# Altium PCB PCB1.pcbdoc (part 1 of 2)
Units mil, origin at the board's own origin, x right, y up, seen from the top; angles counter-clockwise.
Board outline 2755.9 x 2755.9 mil, 4 copper layers (Top Layer, GND02, PWR03, Bottom Layer), stack 64.1 mil thick; 209 components, 118 nets, 572 pads, 665 vias.
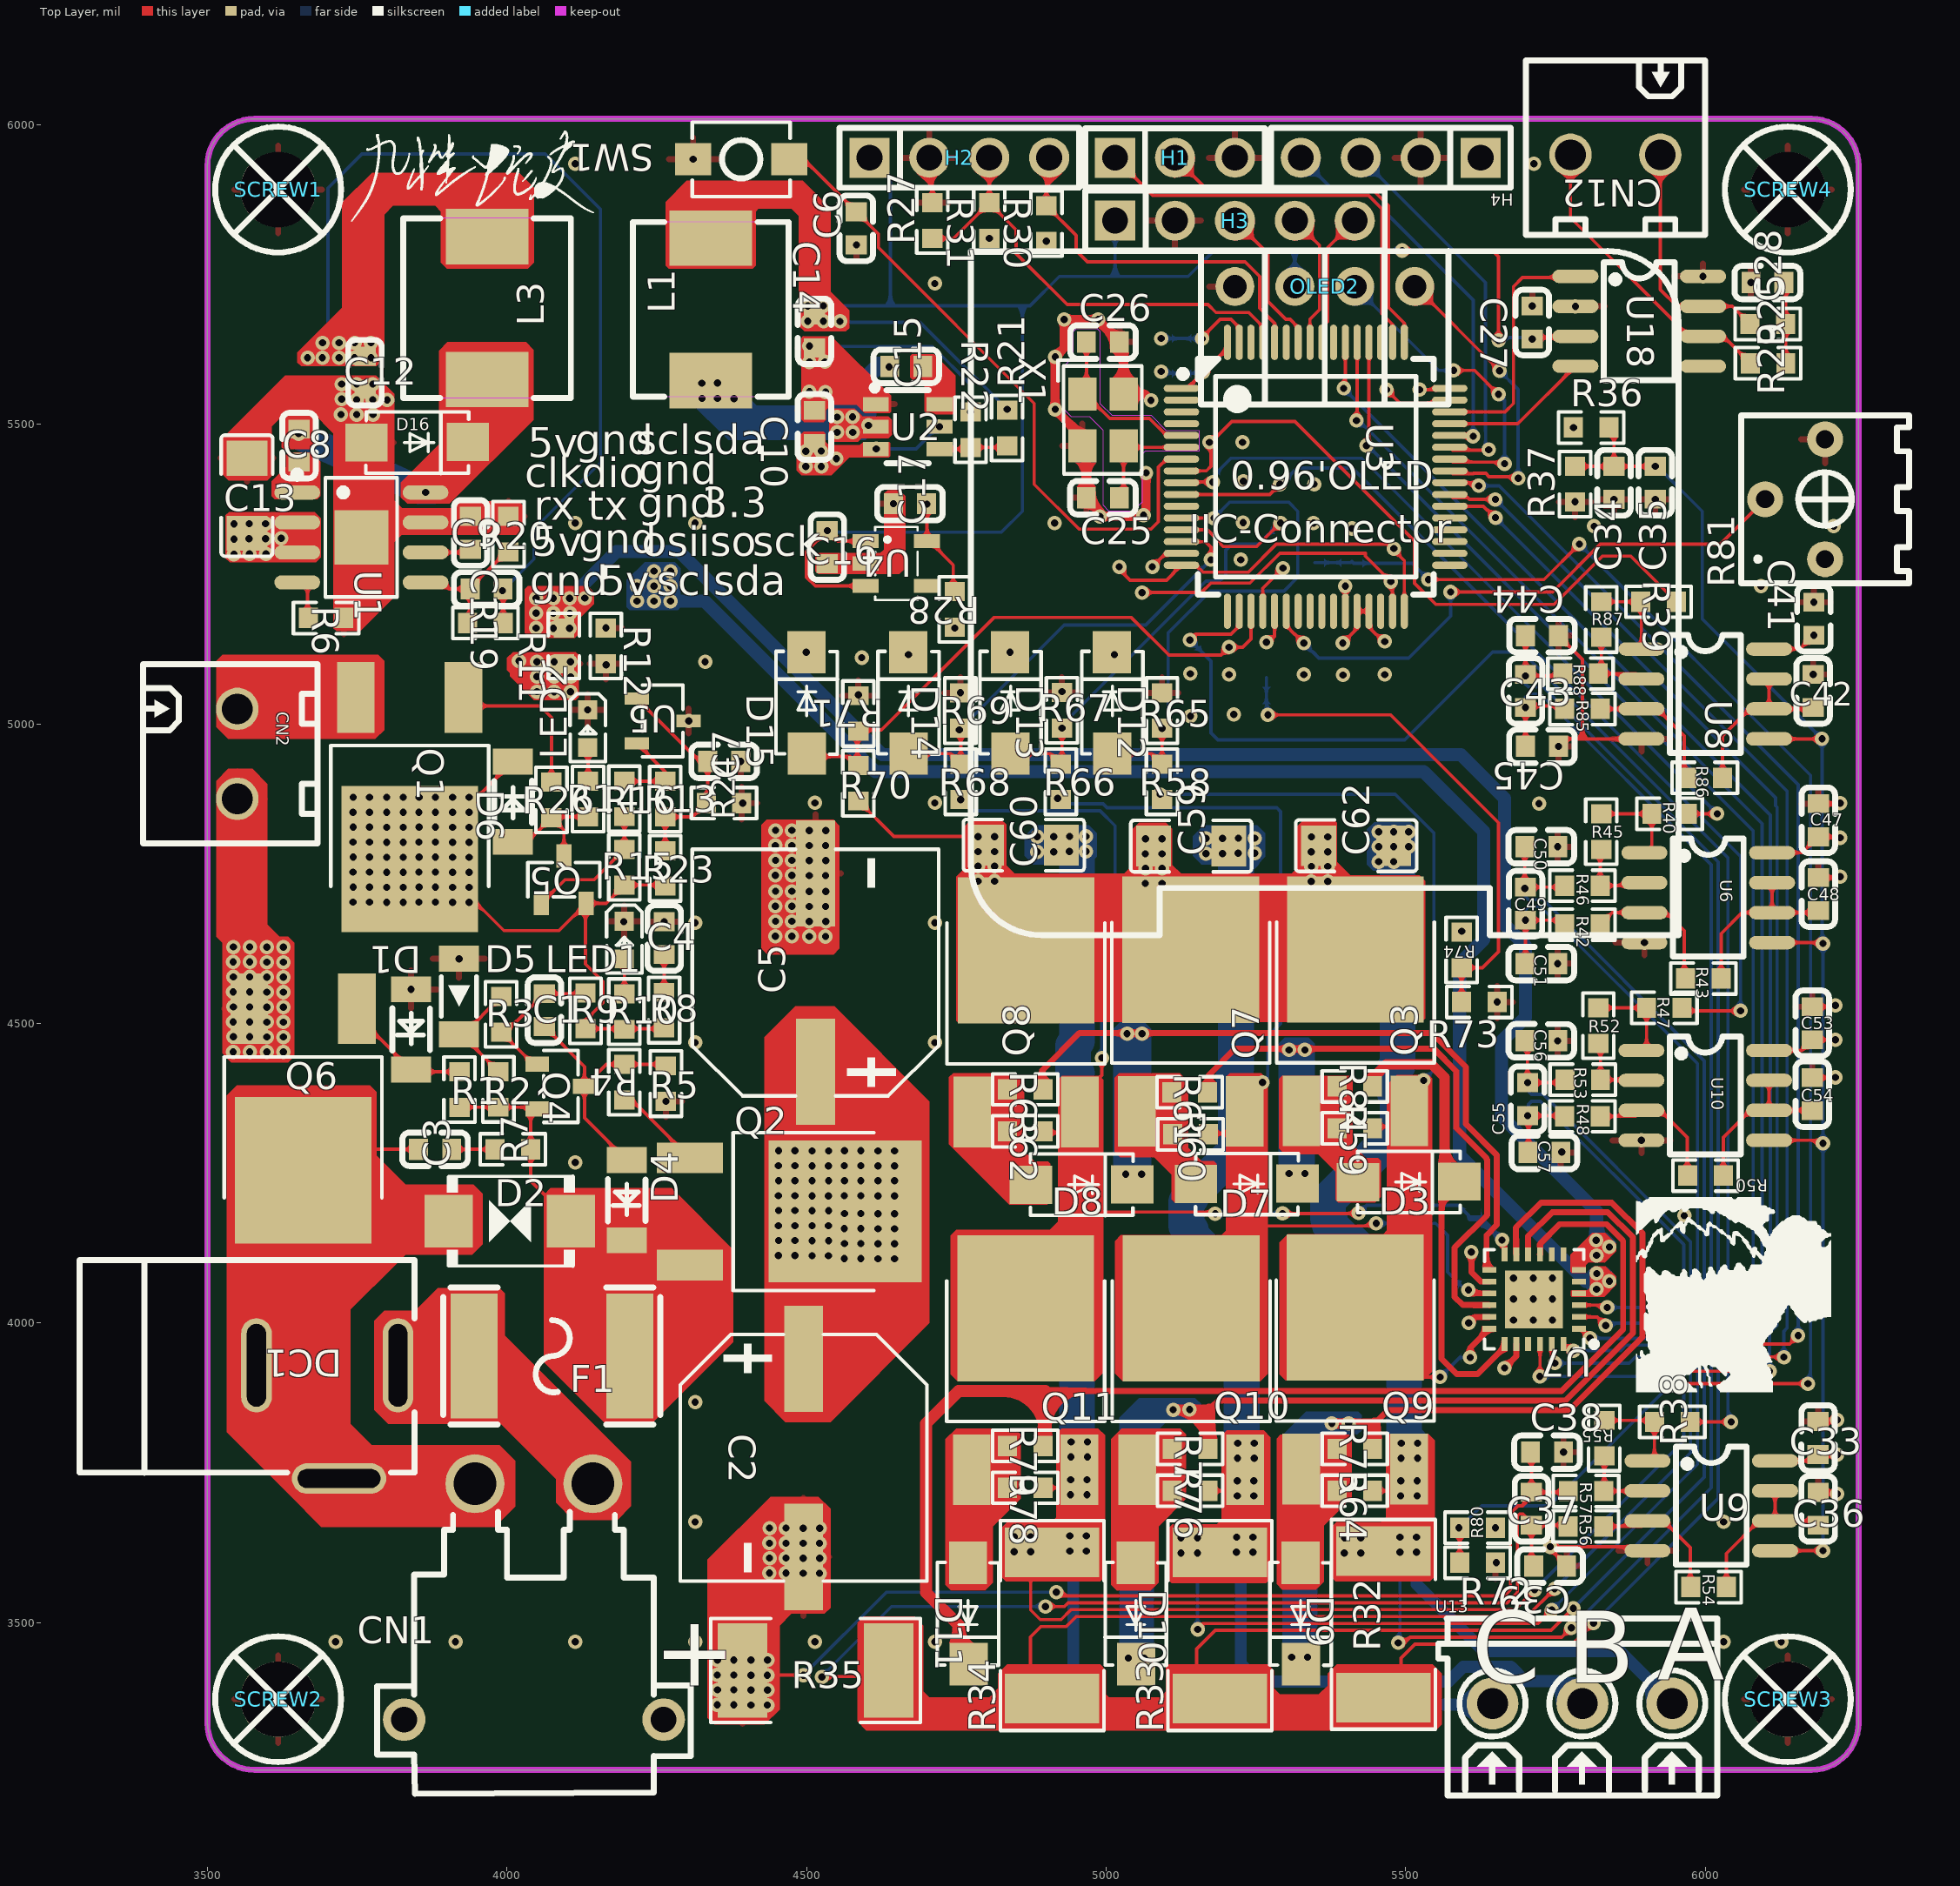
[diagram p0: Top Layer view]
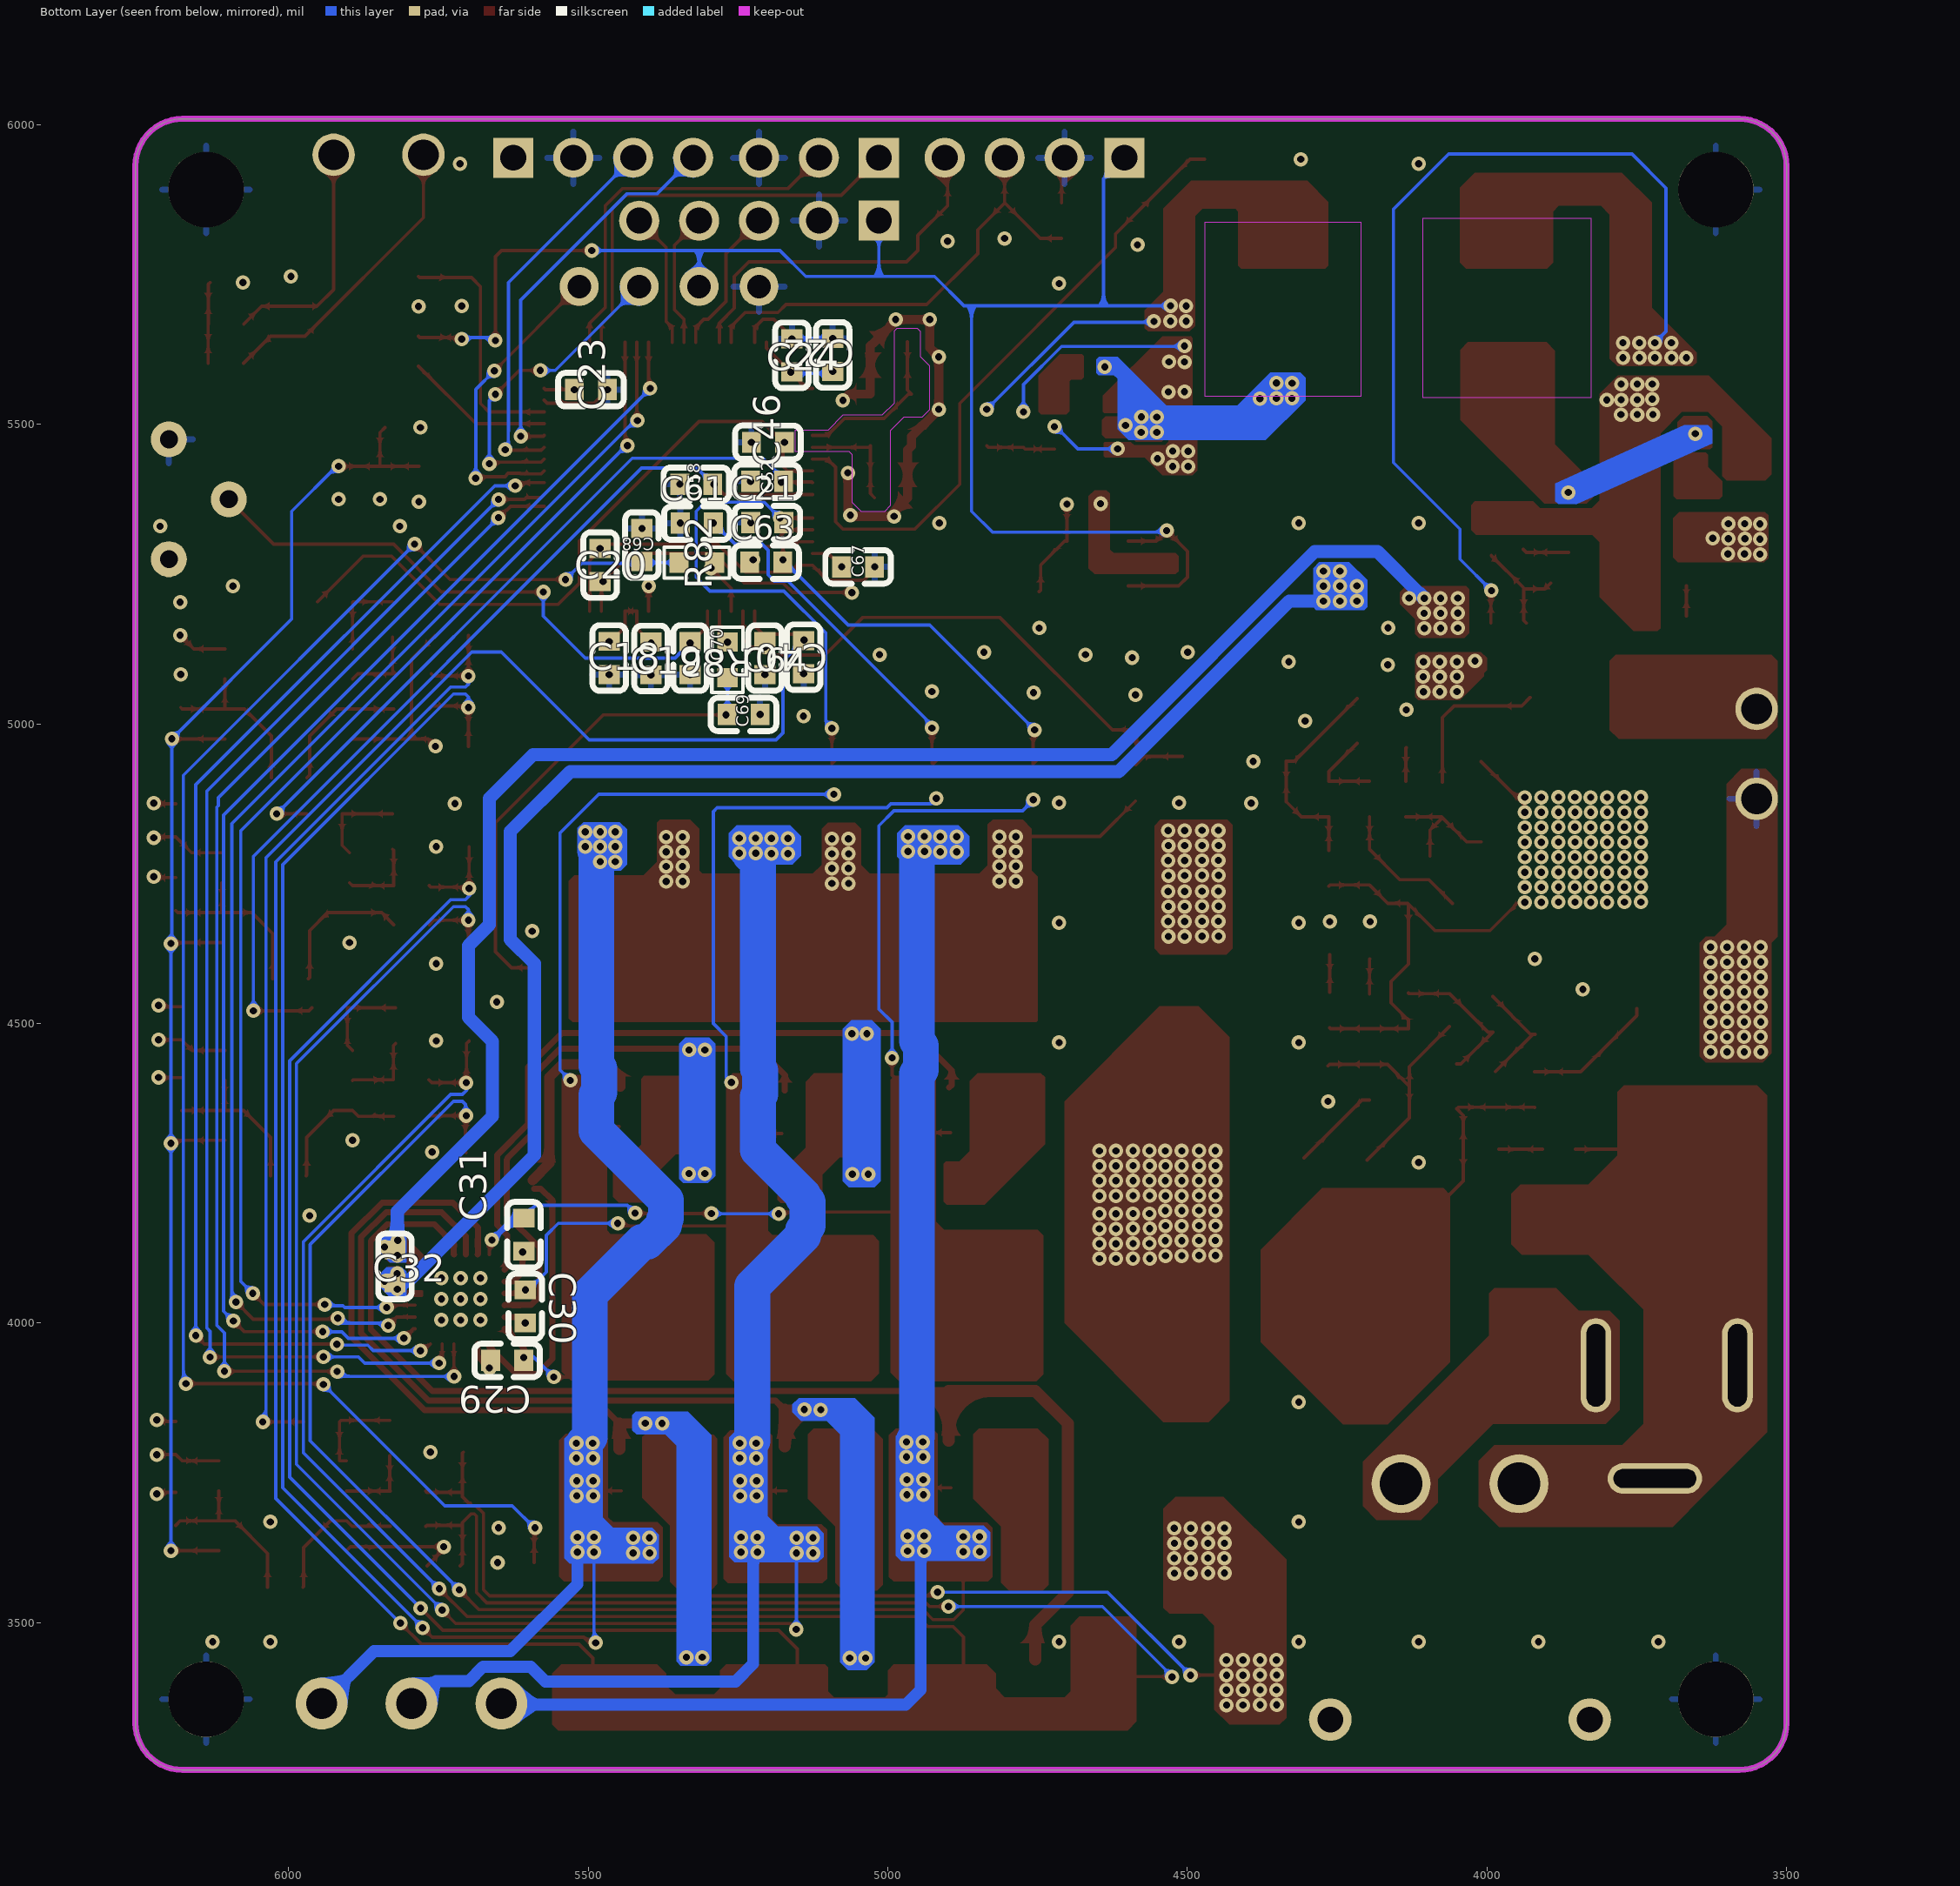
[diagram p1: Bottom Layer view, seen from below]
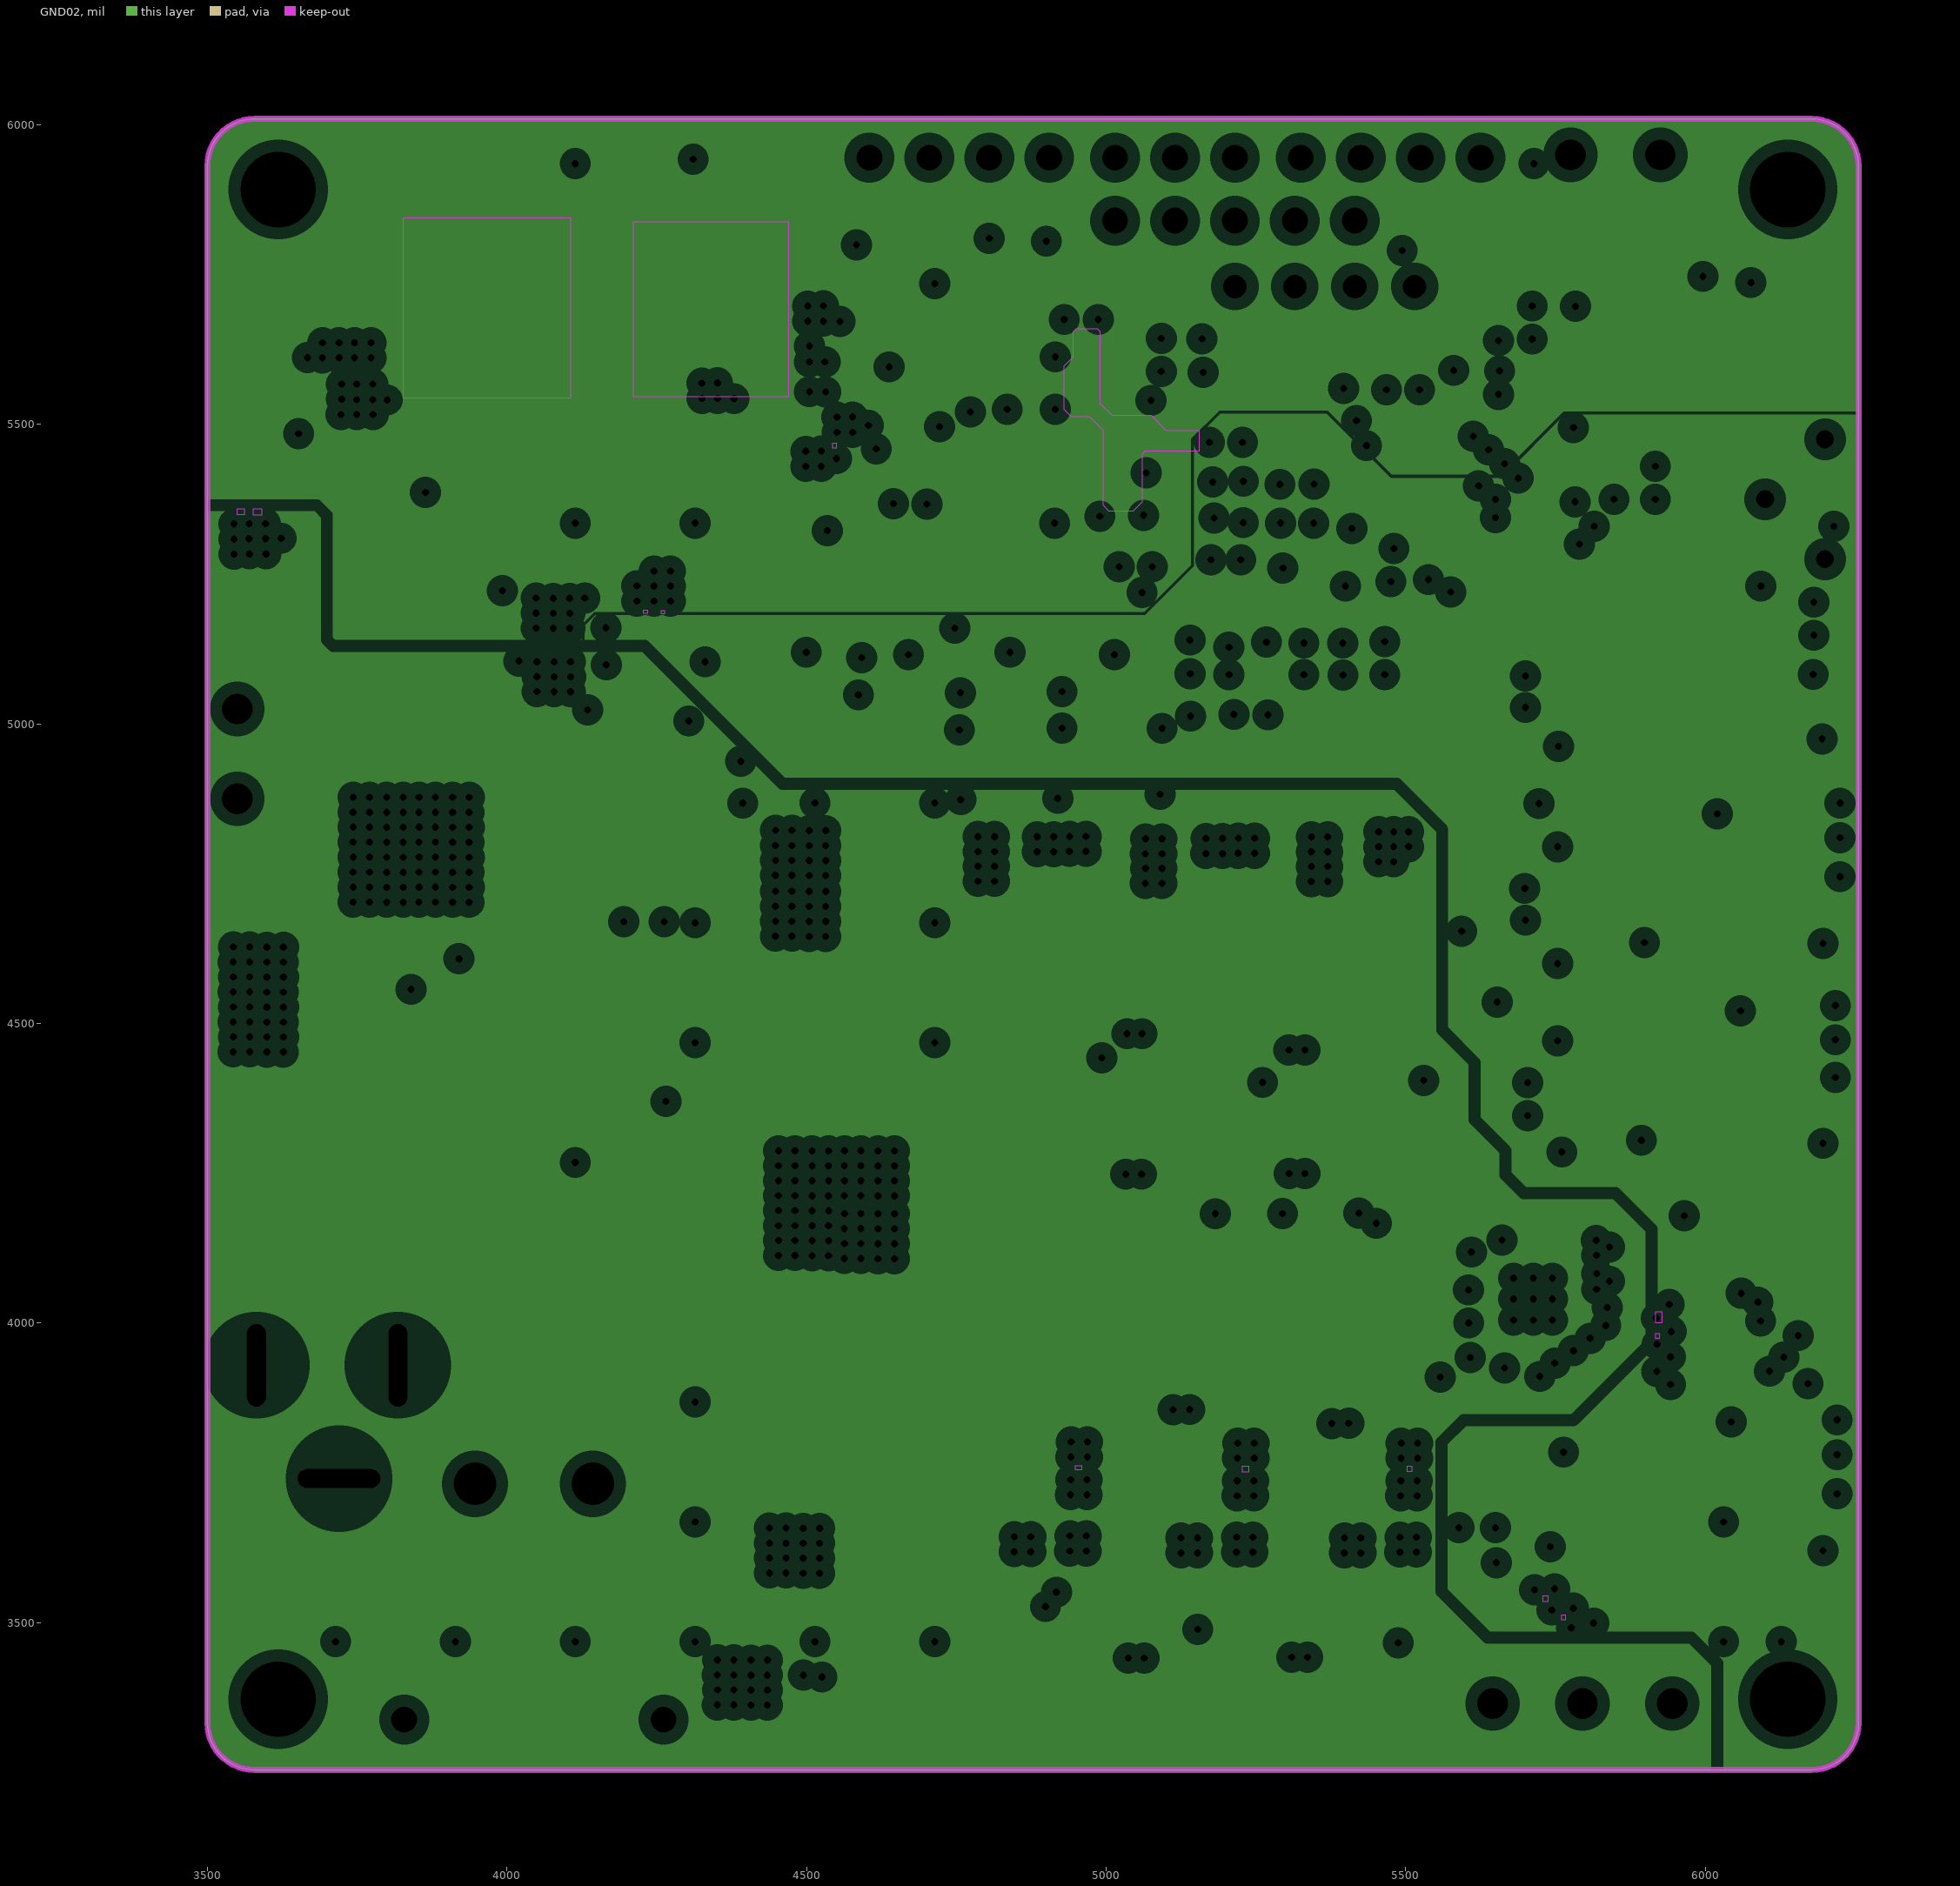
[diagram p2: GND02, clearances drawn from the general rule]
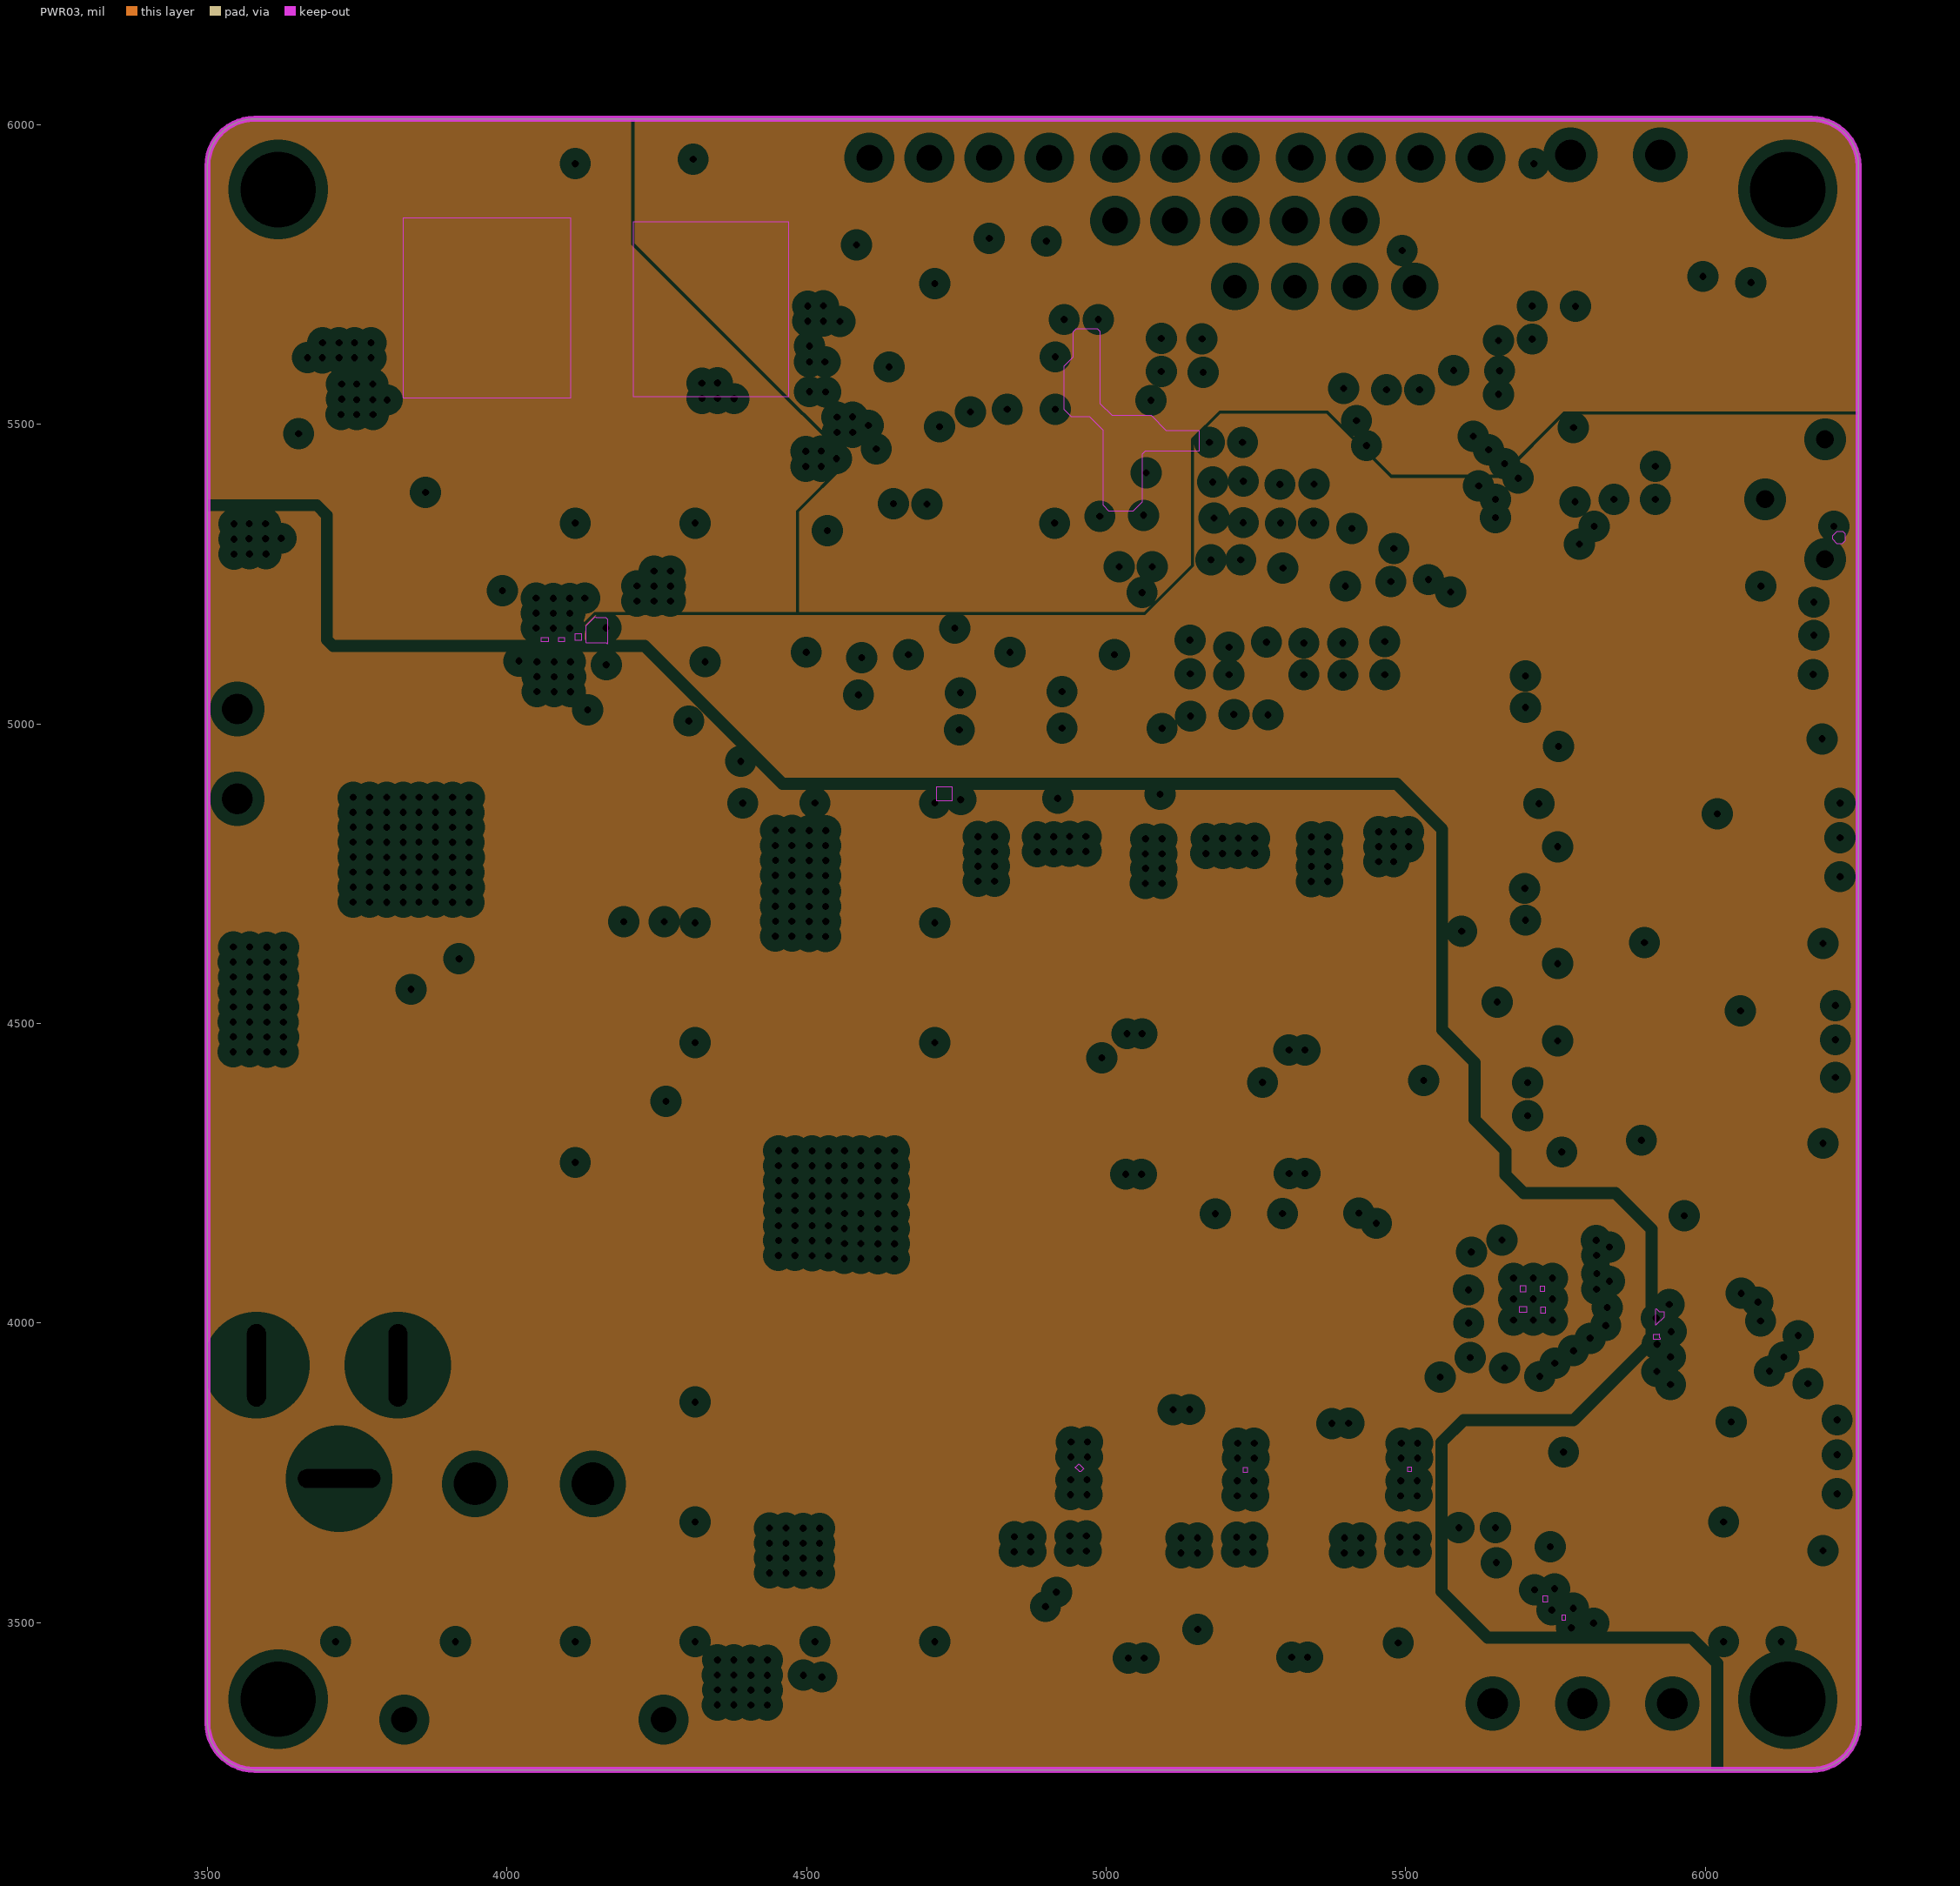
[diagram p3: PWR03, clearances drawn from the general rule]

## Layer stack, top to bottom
Top Layer: signal copper 1.4
Dielectric1: surface 8.3, 7628 RC49% 8.6mil, Dk 0
GND02: plane copper 1.4
Dielectric2: surface 41.9, 1.1mm H/HOZ Copper, Dk 0
PWR03: plane copper 1.4
Dielectric3: surface 8.3, 7628 RC49% 8.6mil, Dk 0
Bottom Layer: signal copper 1.4

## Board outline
3578.7,6010 ccw(c3578.7,5931.3) 3500,5931.3 3500,3332.8 ccw(c3578.7,3332.8) 3578.7,3254.1 6177.2,3254.1 ccw(c6177.2,3332.8) 6255.9,3332.8 6255.9,5931.3 ccw(c6177.2,5931.3) 6177.2,6010 3578.7,6010

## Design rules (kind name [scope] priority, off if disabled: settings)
BoardOutlineClearance copperThickness1oz [All] p0: genericclearance=10 ignorepadtopadclearanceinfootprint=FALSE except(0: Arc-SplitContinuation Track-SplitContinuation SMDPad-SplitContinuation THPad-SplitContinuation Via-SplitContinuation Fill-SplitContinuation Poly-SplitContinuation Region-SplitContinuation Text-SplitContinuation)
BoardOutlineClearance copperThickness2oz [All] p0: genericclearance=10 ignorepadtopadclearanceinfootprint=FALSE except(0: Arc-SplitContinuation Track-SplitContinuation SMDPad-SplitContinuation THPad-SplitContinuation Via-SplitContinuation Fill-SplitContinuation Poly-SplitContinuation Region-SplitContinuation Text-SplitContinuation)
BoardOutlineClearance copperThicknessInner0.5oz [All] p0: genericclearance=10 ignorepadtopadclearanceinfootprint=FALSE except(0: Arc-SplitContinuation Track-SplitContinuation SMDPad-SplitContinuation THPad-SplitContinuation Via-SplitContinuation Fill-SplitContinuation Poly-SplitContinuation Region-SplitContinuation Text-SplitContinuation)
BoardOutlineClearance 3W [All] p0: genericclearance=10 ignorepadtopadclearanceinfootprint=FALSE except(0: Arc-SplitContinuation Track-SplitContinuation SMDPad-SplitContinuation THPad-SplitContinuation Via-SplitContinuation Fill-SplitContinuation Poly-SplitContinuation Region-SplitContinuation Text-SplitContinuation)
BoardOutlineClearance otherClearance [All] p0: genericclearance=10 ignorepadtopadclearanceinfootprint=FALSE except(0: Arc-SplitContinuation Track-SplitContinuation SMDPad-SplitContinuation THPad-SplitContinuation Via-SplitContinuation Fill-SplitContinuation Poly-SplitContinuation Region-SplitContinuation Text-SplitContinuation)
Clearance copperThickness1oz [All] p1: gap=7 ignorepadtopadclearanceinfootprint=FALSE
Clearance copperThickness2oz [All] p1: gap=7 ignorepadtopadclearanceinfootprint=FALSE
Clearance copperThicknessInner0.5oz [All] p1: gap=7 ignorepadtopadclearanceinfootprint=FALSE
Clearance 3W [(InNet('PF1-OSC_OUT') OR InNet('PF0-OSC_IN') OR InNet('ADC_I') OR InNet('ADC_AI') OR InNet('ADC_BI') OR InNet('ADC_CI') OR InNet('ADC_AU') OR InNet('ADC_BU') OR InNet('ADC_CU') OR InNet('ADC_U') OR InNet('ADC_SPEED') OR InNet('ADC_NTC1') OR InNet('ADC_NTC2'))] p1: gap=7 ignorepadtopadclearanceinfootprint=FALSE
Clearance otherClearance [All] p1: gap=7 ignorepadtopadclearanceinfootprint=FALSE
DiffPairsRouting differentialPair [All] p1: maxuncoupledlength=10 minlimit=5.9843 maxlimit=Infinity mostfreqgap=5.9843 toplayer_minwidth=5 toplayer_prefwidth=10 toplayer_maxwidth=100 bottomlayer_minwidth=5 bottomlayer_prefwidth=10 bottomlayer_maxwidth=100
PasteMaskExpansion pasteMaskExpansion [All] p1: expansion=0
PlaneConnect innerPlane [All] p1: planeconnectstyle=Relief reliefexpansion=20 reliefentries=4 reliefconductorwidth=10 reliefairgap=10
PolygonConnect copperRegion [All] p1: connectstyle=Relief reliefentries=4 reliefconductorwidth=10 polygonreliefangle="90 Angle" airgapwidth=10
RoutingVias viaSize [All] p1: viastyle="Through Hole" holewidth=12 minholewidth=7.874 maxholewidth=248.0314 width=12 minwidth=7.874 maxwidth=248.0314
RoutingVias 大过孔 [All] p1: viastyle="Through Hole" holewidth=12.0078 minholewidth=11.811 maxholewidth=248.0316 width=12.0078 minwidth=11.811 maxwidth=248.0316
SolderMaskExpansion solderMaskExpansion [IsVia] p1: useseparateexpansions=TRUE expansion=-1000 expansionbottom=-1000
SolderMaskExpansion solderMaskExpansion [All] p2: useseparateexpansions=TRUE expansion=2.0079 expansionbottom=2.0079
Width copperThickness1oz [All] p1: maxlimit=100 minlimit=4 preferedwidth=6
Width copperThickness2oz [All] p1: maxlimit=100 minlimit=8 preferedwidth=10
Width copperThickness0.5oz [All] p1: maxlimit=100 minlimit=4 preferedwidth=10

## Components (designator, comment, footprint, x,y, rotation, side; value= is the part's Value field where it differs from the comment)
C1 "100nF" C0603#1 4062.6,4522.3 r90 top
C2 "220uF" CAP-SMD_BD10.0-L10.3-W10.3-FD-LS11.0 4495,3775 r270 top
C3 "100nF" C0603#2 3880,4290 r0 top
C4 "100nF" C0603#3 4262.4,4642.4 r270 top
C5 "220uF" CAP-SMD_BD10.0-L10.3-W10.3-FD-LS11.0 4515,4585 r90 top
C6 "100nF" C0603#3 4583.2,5827.2 r90 top
C7 "100nF" C0603#1 4362.6,4937.6 r180 top
C8 "100nF" C0603#3 3652.8,5464.5 r90 top
C9 "100nF" C0603#2 3939.3,5318.9 r270 top
C10 "100nF" C0603#3 4513.2,5495.6 r270 top
C11 "100nF" C0603#3 3966.2,5225.3 r0 top
C12 "100nF" C0603#3 3763.1,5586.2 r90 top
C13 "100nF" C1206 3566.1,5380.9 r270 top
C14 "100nF" C0603#2 4513.3,5655.2 r90 top
C15 "100nF" C0603#2 4666.4,5596.8 r180 top
C16 "100nF" C0603#3 4534.6,5295.1 r90 top
C17 "100nF" C0603#3 4672.6,5367.6 r0 top
C18 "100nF" C0603#2 5465,5110 r270 bottom
C19 "100nF" C0603#1 5395.3,5109.3 r270 bottom
C20 "100nF" C0603#3 5480.3,5265.1 r270 bottom
C21 "100nF" C0603#3 5201.1,5336.1 r180 bottom
C22 "100nF" C0603#3 5092.1,5615.7 r270 bottom
C23 "100nF" C0603#3 5495.6,5557.9 r0 bottom
C24 "100nF" C0603#3 5160,5615.2 r270 bottom
C25 "100nF" C0603#1 4994.5,5377.5 r0 top
C26 "100nF" C0603#3 4994.8,5637.5 r0 top
C27 "100nF" C0603#1 5711.3,5670 r270 top
C28 "100nF" C0603#3 6103.8,5736.8 r0 top
C29 "100nF" C0603#2 5635.3,3937.6 r0 bottom
C30 "100nF" C0603#1 5605.2,4027.6 r90 bottom
C31 "100nF" C0603#1 5607.4,4147.4 r90 bottom
C32 "100nF" C0603#1 5822.6,4094.6 r270 bottom
C33 "100nF" C0603#2 6188.4,3808.1 r270 top
C34 "100nF" C0603#1 5847.6,5402.4 r90 top
C35 "100nF" C0603#3 5916.6,5402.6 r90 top
C36 "100nF" C0603#3 6188.5,3689.9 r270 top
C37 "100nF" C0603#2 5710,3690 r90 top
C38 "100nF" C0603#3 5735.9,3784.6 r180 top
C39 "100nF" C0603#1 5741.2,3594.6 r180 top
C40 "100nF" C0603#1 5140.4,5111.3 r90 bottom
C41 "100nF" C0603#3 6181.2,5175.5 r270 top
C42 "100nF" C0603#2 6180.1,5055 r270 top
C43 "100nF" C0603#2 5700,5055 r90 top
C44 "100nF" C0603#1 5727.6,5147.4 r180 top
C45 "100nF" C0603#3 5727.4,4962.6 r180 top
C46 "100nF" C0603#3 5200.1,5470 r180 bottom
C47 "100nF" C0603#2 6188.7,4839.2 r270 top
C48 "100nF" C0603#2 6188.7,4715.9 r270 top
C49 "100nF" C0603#2 5700,4700 r90 top
C50 "100nF" C0603#3 5726.2,4795 r180 top
C51 "100nF" C0603#3 5726.2,4600 r180 top
C52 "100nF" C0603#2 5201.6,5405 r180 bottom
C53 "100nF" C0603#3 6178.7,4500.3 r270 top
C54 "100nF" C0603#3 6178.7,4382 r270 top
C55 "100nF" C0603#3 5703.6,4373.7 r90 top
C56 "100nF" C0603#3 5726.2,4471.1 r180 top
C57 "100nF" C0603#3 5731.4,4284.6 r180 top
C58 "100nF" C0603#3 5319.6,5400.1 r180 bottom
C59 "100nF" C1206 5142,4796 r0 top
C60 "100nF" C1206 4862.7,4797.7 r0 top
C61 "100nF" C0603#1 5318.8,5335.1 r180 bottom
C62 "100nF" C1206 5417.4,4796.7 r0 top
C63 "100nF" C0603#1 5202.9,5270.1 r180 bottom
C64 "100nF" C0603#2 5205,5110 r90 bottom
C67 "100nF" C0603#3 5049.6,5262.2 r0 bottom
C68 "100nF" C0603#3 5410.4,5298.6 r270 bottom
C69 "100nF" C0603#1 5240.8,5015.8 r0 bottom
C70 "100nF" C0603#3 5330,5109.9 r90 bottom
CN1 "XT30PW-M30.G.Y" CONN-TH_XT30PW-M 4045,3535 r0 top
CN2 "MX128L-3.81-02P-GN01-Cu-Y-A" CONN-TH_2P-P3.81_MX128L-3.81-GN01-02P-CU-Y-A 3550,4950 r270 top
CN12 "MX128L-3.81-02P-GN01-Cu-Y-A" CONN-TH_2P-P3.81_MX128L-3.81-GN01-02P-CU-Y-A 5850,5950 r180 top
D1 "ZMM15V" LL-34_L3.5-W1.5-RD-2 3840,4490 r90 top
D2 "SMBJ28CA" SMB_L4.6-W3.6-LS5.4-BI 4005,4170 r0 top
D3 "SS54" SMA_L4.3-W2.6-LS5.0-FD#1 5505.2,4235.7 r0 top
D4 "ZMM15V" LL-34_L3.5-W1.5-RD-2 4200,4205 r90 top
D5 "ZMM30V" LL-34_L3.5-W1.5-RD 3920,4545 r90 top
D6 "ZMM15V" LL-34_L3.5-W1.5-RD-2 4010,4870 r270 top
D7 "SS54" SMA_L4.3-W2.6-LS5.0-FD#2 5234.7,4232.5 r0 top
D8 "SS54" SMA_L4.3-W2.6-LS5.0-FD#3 4959,4231.3 r0 top
D9 "SS54" SMA_L4.3-W2.6-LS5.0-FD#4 5325,3515 r270 top
D10 "SS54" SMA_L4.3-W2.6-LS5.0-FD#4 5050,3515 r270 top
D11 "SS54" SMA_L4.3-W2.6-LS5.0-FD#4 4770,3515 r270 top
D12 "SS54" SMA_L4.3-W2.6-LS5.0-FD#4 5010,5035 r90 top
D13 "SS54" SMA_L4.3-W2.6-LS5.0-FD#4 4840,5035 r90 top
D14 "SS54" SMA_L4.3-W2.6-LS5.0-FD#4 4670,5035 r90 top
D15 "SS54" SMA_L4.3-W2.6-LS5.0-FD#4 4500,5035 r90 top
D16 "SS54" SMA_L4.3-W2.6-LS5.0-FD#4 3850,5470 r0 top
DC1 "" DC-2.0 3695,3940 r180 top
F1 "SMD2920P185TF" F2920 4075,3945 r0 top
H1 "" HDR-TH_3P-P2.54-V-M 5115,5945 r0 top
H2 "" HDR-TH_4P-P2.54-V-M 4755,5945 r0 top
H3 "" HDR-TH_5P-P2.54-V-M 5215,5840 r0 top
H4 "" HDR-TH_4P-P2.54-V-M 5475,5945 r180 top
L1 "10uH" IND-SMD_L7.4-W6.6_SRG0630 4340.3,5692 r90 top
L3 "22uH" IND-SMD_L7.5-W6.6_GSM0650 3966.7,5694.1 r90 top
LED1 "" LED_0603 4196,4637.2 r270 top
LED2 "" LED_0603 4135,4990 r270 top
OLED2 "0.96OLED_4P_MODULE_JX" 0.96OLED_4P 5365,5730 r0 top
Q1 "NCE6050KA" TO-252-2_L6.6-W6.1-P4.57-LS10.1-TL-CW#1 3837.7,4909.5 r270 top
Q2 "NCE60P25K" TO-252-2_L6.6-W6.1-P4.57-LS9.9-TL-CW 4434.9,4186.4 r0 top
Q3 "NCE6050KA" TO-252-2_L6.6-W6.1-P4.57-LS10.1-TL-CW#2 5416.1,4488.8 r90 top
Q4 "MMBT3906" SOT-23-3_L2.9-W1.3-P1.90-LS2.4-BR 4090,4395 r180 top
Q5 "MMBT3906" SOT-23-3_L2.9-W1.3-P1.90-LS2.4-BR 4095,4740 r270 top
Q6 "NCE6050KA" TO-252-2_L6.6-W6.1-P4.57-LS10.1-TL-CW#2 3659.8,4389.8 r270 top
Q7 "NCE6050KA" TO-252-2_L6.6-W6.1-P4.57-LS10.1-TL-CW#1 5141.4,4488.2 r90 top
Q8 "NCE6050KA" TO-252-2_L6.6-W6.1-P4.57-LS10.1-TL-CW#1 4866.4,4487.1 r90 top
Q9 "NCE6050KA" TO-252-2_L6.6-W6.1-P4.57-LS10.1-TL-CW#2 5415.8,3890.9 r90 top
Q10 "NCE6050KA" TO-252-2_L6.6-W6.1-P4.57-LS10.1-TL-CW#1 5142,3889.9 r90 top
Q11 "NCE6050KA" TO-252-2_L6.6-W6.1-P4.57-LS10.1-TL-CW#1 4865.8,3889.9 r90 top
R1 "10K" R0603#1 3920.7,4389.7 r270 top
R2 "10K" R0603#2 3985.7,4390 r270 top
R3 "10K" R0603#3 3990.3,4515.3 r270 top
R4 "10K" R0603#1 4195.9,4402.1 r270 top
R5 "10K" R0603#3 4265.3,4399.7 r90 top
R6 "10K" R0603#1 3698.2,5176.8 r180 top
R7 "10K" R0603#2 4010,4290 r0 top
R8 "10K" R0603#3 4262.3,4522.2 r270 top
R9 "10K" R0603#3 4131,4521 r270 top
R10 "10K" R0603#1 4195.9,4519.9 r270 top
R11 "10K" R0603#2 4095,5130 r270 top
R12 "10K" R0603#2 4165,5130 r270 top
R13 "10K" R0603#3 4264.1,4874.6 r90 top
R14 "10K" R0603#3 4135.3,4874.7 r90 top
R15 "10K" R0603#3 4195.9,4760.7 r270 top
R16 "10K" R0603#2 4195.9,4875 r90 top
R19 "10K" R0603#3 3964,5168.4 r0 top
R20 "10K" R0603#2 4002.4,5316.7 r270 top
R21 "10K" R0603#1 4834.8,5493.7 r90 top
R22 "10K" R0603#2 4773.7,5491.2 r270 top
R23 "10K" R0603#1 4264.1,4758.9 r270 top
R24 "10K" R0603#1 4362.3,4867.8 r180 top
R25 "10K" R0603#3 6104.4,5667.4 r180 top
R26 "10K" R0603#1 4074.3,4873 r90 top
R27 "10K" R0603#2 4710,5840 r90 top
R28 "10K" R0603#2 4747.4,5191.3 r270 top
R29 "10K" R0603#3 6104.8,5602 r0 top
R30 "10K" R0603#3 4900.3,5835.3 r270 top
R31 "10K" R0603#2 4805,5840 r270 top
R32 "330mΩ" RES-SMD_L6.4-W3.2-JER2512XXXXXX#1 5463,3497 r90 top
R33 "330mΩ" RES-SMD_L6.4-W3.2-JER2512XXXXXX#2 5190,3495 r90 top
R34 "330mΩ" RES-SMD_L6.4-W3.2-JER2512XXXXXX#2 4910,3495 r90 top
R35 "330mΩ" RES-SMD_L6.4-W3.2-JER2512XXXXXX#2 4515,3420 r0 top
R36 "10K" R0603#1 5809.7,5494.7 r180 top
R37 "10K" R0603#1 5782.7,5400.3 r90 top
R38 "10K" R0603#2 5945,3835 r180 top
R39 "10K" R0603#1 5922.2,5203.9 r180 top
R40 "10K" R0603#3 5940.4,4850 r180 top
R42 "10K" R0603#2 5795,4665 r180 top
R43 "10K" R0603#2 5996.8,4575 r180 top
R45 "10K" R0603#3 5826.5,4820.3 r270 top
R46 "10K" R0603#2 5795,4730 r180 top
R47 "10K" R0603#2 5931.8,4526.1 r180 top
R48 "10K" R0603#2 5795,4345 r180 top
R50 "10K" R0603#3 6000.4,4246.1 r180 top
R52 "10K" R0603#3 5821.5,4496.4 r270 top
R53 "10K" R0603#3 5795.4,4406.1 r180 top
R54 "10K" R0603#1 6005.7,3559.2 r0 top
R55 "10K" R0603#1 5831.4,3807.9 r270 top
R56 "10K" R0603#1 5800.7,3660.7 r180 top
R57 "10K" R0603#1 5801.1,3719.6 r180 top
R58 "10K" R0603#3 5093.3,4903.3 r270 top
R59 "10K" R0603#2 5415,4325 r180 top
R60 "10K" R0603#1 5140.8,4315 r180 top
R61 "10K" R0603#3 5139.3,4385 r180 top
R62 "10K" R0603#2 4865,4320 r180 top
R63 "10K" R0603#2 4865,4390 r180 top
R64 "10K" R0603#2 5415,3720 r180 top
R65 "10K" R0603#1 5093.3,5022.4 r270 top
R66 "10K" R0603#3 4924.3,4903.3 r270 top
R67 "10K" R0603#1 4926.3,5022.7 r270 top
R68 "10K" R0603#3 4757.4,4903.3 r270 top
R69 "10K" R0603#1 4756.7,5022.4 r270 top
R70 "10K" R0603#3 4586.5,4900.9 r270 top
R71 "10K" R0603#3 4586.5,5017.3 r270 top
R72 "HNTC0603-103F3450FA" R0603#2 5620,3600 r180 top
R73 "HNTC0603-103F3450FA" R0603#3 5623,4535.8 r180 top
R74 "10K" R0603#3 5593.4,4622.8 r90 top
R75 "10K" R0603#2 5415,3790 r180 top
R76 "10K" R0603#2 5140,3720 r180 top
R77 "10K" R0603#2 5140,3790 r180 top
R78 "10K" R0603#2 4865,3725 r180 top
R79 "10K" R0603#2 4865,3795 r180 top
R80 "10K" R0603#2 5620,3658.4 r0 top
R81 "10kΩ" RES-ADJ-TH_3362P 6150,5375 r90 top
R82 "10K" R0603#3 5318.6,5269.2 r180 bottom
R83 "10K" R0603#1 5267.7,5106.8 r90 bottom
R84 "10K" R0603#2 5415,4395 r180 top
R85 "10K" R0603#2 5795,5025 r180 top
R86 "10K" R0603#3 5999.3,4910 r180 top
R87 "10K" R0603#3 5826.5,5174.2 r270 top
R88 "10K" R0603#2 5791.8,5083.9 r180 top
SCREW1 "" M3螺丝 3618.1,5891.9 r0 top
SCREW2 "" M3螺丝 3618.1,3372.2 r0 top
SCREW3 "" M3螺丝 6137.8,3372.2 r0 top
SCREW4 "" M3螺丝 6137.8,5891.9 r0 top
SW1 "" Key_SMD_3x4x2 4390.9,5942.5 r0 top
U1 "LMR16030SDDAR" SOIC-8_L4.9-W3.9-P1.27-LS6.0-BL-EP2.3 3757,5311.3 r270 top
U2 "TPS562201DDCR" SOT-23-6_L2.9-W1.6-P0.95-LS2.8-BR 4668.7,5496.2 r180 top
U3 "STM32G431RBT6" LQFP-64_L10.0-W10.0-P0.50-LS12.0-BL 5349.6,5412.5 r270 top
U4 "LP5907MFX-3.3/NOPB" SOT-23-5_L3.0-W1.7-P0.95-LS2.8-BR 4649.9,5267.6 r180 top
U5 "TL431A" SOT-23-3_L3.0-W1.7-P0.95-LS2.9-BR 4260,5005 r180 top
U6 "TLV9062IDR" SOIC-8_L5.0-W4.0-P1.27-LS6.0-BL 6005,4710 r270 top
U7 "DRV8300DRGER" VQFN-24_L4.0-W4.0-P0.50-TL-EP2.5 5714.3,4039.7 r180 top
U8 "TLV9062IDR" SOIC-8_L5.0-W4.0-P1.27-LS6.0-BL 6000,5050 r270 top
U9 "TLV9062IDR" SOIC-8_L5.0-W4.0-P1.27-LS6.0-BL 6010,3695 r270 top
U10 "TLV9062IDR" SOIC-8_L5.0-W4.0-P1.27-LS6.0-BL 6000,4380 r270 top
U13 "KF128L-3.81-3P" CONN-TH_3P-P3.81_KF128L-3.81-3P 5795,3365 r0 top
U18 "TJA1050T/CM,118" SOIC-8_L5.0-W4.0-P1.27-LS6.0-BL 5889.8,5672 r270 top
X1 "8MHz" CRYSTAL-SMD_4P-L3.2-W2.5-BL-1 4994.8,5507.3 r270 top

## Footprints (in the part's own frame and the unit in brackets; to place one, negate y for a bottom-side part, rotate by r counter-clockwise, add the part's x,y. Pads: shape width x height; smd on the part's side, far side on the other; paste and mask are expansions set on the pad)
0.96OLED_4P [mil]
  round 65 hole 39.4: 1(-150,0) 2(-50,0.1) 3(50,0.1) 4(150,0.1)
  silkscreen extent -591,-1083 591,59
C0603#1 [mil]
  rect 31.5x35.4 smd: 1(-27.5,0) 2(27.6,0)
  silkscreen extent -55,-28 55,28
C0603#2 [mil]
  rect 31.5x35.4 smd: 1(-27.6,0) 2(27.6,0)
  silkscreen extent -55,-28 55,28
C0603#3 [mil]
  rect 31.5x35.4 smd: 1(-27.6,0) 2(27.5,0)
  silkscreen extent -55,-28 55,28
C1206 [mil]
  rect 58.5x68 smd paste-3937 mask+2: 1(-62.7,0) 2(62.7,0)
  silkscreen extent -101,-43 101,43
CAP-SMD_BD10.0-L10.3-W10.3-FD-LS11.0 [mil]
  rect 177.2x65 smd: 1(-165.4,0) 2(165.4,0)
  silkscreen extent -206,-206 206,206
CONN-TH_2P-P3.81_MX128L-3.81-GN01-02P-CU-Y-A [mil]
  round 70.9 hole 51.2 paste+0 mask+2: 1(-75,0) 2(75,0)
  silkscreen extent -150,-158 150,134
CONN-TH_3P-P3.81_KF128L-3.81-3P [mil]
  round 86.6 hole 51.2 paste+0 mask+2: 1(-150,0) 2(0,0) 3(150,0)
  silkscreen extent -241,-154 225,142
CONN-TH_XT30PW-M [mil]
  round 98.4 hole 70.9: 1(-98.4,196.8) 2(98.4,196.8)
  round 70.9 hole 43.3: 3(216.5,-196.9) 4(-216.5,-196.9)
  silkscreen extent -262,-321 262,150
CRYSTAL-SMD_4P-L3.2-W2.5-BL-1 [mil]
  rect 55.1x47.2 smd: 1(-43.3,-34.4) 2(43.3,-34.4) 3(43.3,34.5) 4(-43.3,34.5)
  silkscreen extent -100,-75 90,65
DC-2.0 [mil]
  oval 157.5x51.2 hole 31.5 slot 137.8 at 0 deg paste+0 mask+2: 2(-24.7,199.5)
  oval 51.2x157.5 hole 31.5 slot 137.8 at 90 deg paste+0 mask+2: 3(113.1,10.5) 4(-123.1,10.5)
  silkscreen extent -151,-165 408,190
F2920 [mil]
  rect 78.7x208.7 smd: 1(-129.9,0) 2(129.9,0)
  silkscreen extent -181,-114 181,114
HDR-TH_3P-P2.54-V-M [mil]
  rect 66.9x66.9 hole 43.3: 1(-100,0)
  round 66.9 hole 43.3: 2(0,0) 3(100,0)
  silkscreen extent -150,-49 150,49
HDR-TH_4P-P2.54-V-M [mil]
  rect 66.9x66.9 hole 43.3: 1(-150,0)
  round 66.9 hole 43.3: 2(-50,0) 3(50,0) 4(150,0)
  silkscreen extent -200,-50 200,50
HDR-TH_5P-P2.54-V-M [mil]
  rect 66.9x66.9 hole 43.3: 1(-200,0)
  round 66.9 hole 43.3: 2(-100,0) 3(0,0) 4(100,0) 5(200,0)
  silkscreen extent -250,-50 250,50
IND-SMD_L7.4-W6.6_SRG0630 [mil]
  rect 92.5x137.8 smd: 1(-119.1,0) 2(119,0)
  silkscreen extent -146,-130 146,130
IND-SMD_L7.5-W6.6_GSM0650 [mil]
  rect 92.5x137.8 smd: 1(-119.1,0) 2(119.1,0)
  silkscreen extent -150,-140 150,140
Key_SMD_3x4x2 [mil]
  rect 60.2x53.5 smd paste+0 mask+2: 1(-80.1,0) 2(80.2,0)
  silkscreen extent -82,-62 82,62
LED_0603 [mil]
  rect 31.5x31.5 smd paste+0 mask+2: 1(-33.5,-0.4) 2(29.5,-0.2)
  silkscreen extent -61,-30 53,30
LL-34_L3.5-W1.5-RD [mil]
  rect 43.3x66.9 smd: 1(-63,0) 2(63,0)
  silkscreen extent -33,-30 33,30
LL-34_L3.5-W1.5-RD-2 [mil]
  rect 43.3x66.9 smd: 1(-66.9,0) 2(66.9,0)
  silkscreen extent -35,-32 35,32
LQFP-64_L10.0-W10.0-P0.50-LS12.0-BL [mil]
  oval 11.8x59.1 smd: 1(-147.6,-223.9) 2(-128,-223.9) 3(-108.3,-223.9) 4(-88.6,-223.9) 5(-68.9,-223.9) 6(-49.2,-223.9) 7(-29.5,-223.9) 8(-9.8,-223.9) 9(9.8,-223.9) 10(29.5,-223.9) 11(49.2,-223.9) 12(68.9,-223.9) 13(88.6,-223.9) 14(108.3,-223.9) 15(127.9,-223.9) 16(147.6,-223.9) 33(147.6,224) 34(127.9,224) 35(108.3,224) 36(88.6,224) 37(68.9,224) 38(49.2,224) 39(29.5,224) 40(9.8,224) 41(-9.8,224) 42(-29.5,224) 43(-49.2,224) 44(-68.9,224) 45(-88.6,224) 46(-108.3,224) 47(-128,224) 48(-147.6,224)
  oval 59.1x11.8 smd: 17(224.4,-147.1) 18(224.4,-127.4) 19(224.4,-107.8) 20(224.4,-88.1) 21(224.4,-68.4) 22(224.4,-48.7) 23(224.4,-29) 24(224.4,-9.3) 25(224.4,10.3) 26(224.4,30) 27(224.4,49.7) 28(224.4,69.4) 29(224.4,89.1) 30(224.4,108.8) 31(224.4,128.5) 32(224.4,148.1) 49(-224.4,148.1) 50(-224.4,128.5) 51(-224.4,108.8) 52(-224.4,89.1) 53(-224.4,69.4) 54(-224.4,49.7) 55(-224.4,30) 56(-224.4,10.3) 57(-224.4,-9.3) 58(-224.4,-29) 59(-224.4,-48.7) 60(-224.4,-68.4) 61(-224.4,-88.1) 62(-224.4,-107.8) 63(-224.4,-127.4) 64(-224.4,-147.1)
  silkscreen extent -197,-227 197,197
M3螺丝 [mil]
  round 126 hole 126 paste+0 mask+4: 1(0,0)
  silkscreen extent -105,-105 105,105
R0603#1 [mil]
  rect 31.8x34 smd paste-3937 mask+2: 1(-29.6,0) 2(29.7,0)
  silkscreen extent -55,-26 55,26
R0603#2 [mil]
  rect 31.8x34 smd paste-3937 mask+2: 1(-29.7,0) 2(29.7,0)
  silkscreen extent -55,-26 55,26
R0603#3 [mil]
  rect 31.8x34 smd paste-3937 mask+2: 1(-29.7,0) 2(29.6,0)
  silkscreen extent -55,-26 55,26
RES-ADJ-TH_3362P [mil]
  round 60 hole 30: 1(-100,-50) 2(0,50) 3(100,-50)
  silkscreen extent -140,-190 140,90
RES-SMD_L6.4-W3.2-JER2512XXXXXX#1 [mil]
  rect 82.7x157.5 smd: 1(-122,0) 2(122.1,0)
  silkscreen extent -175,-87 175,87
RES-SMD_L6.4-W3.2-JER2512XXXXXX#2 [mil]
  rect 82.7x157.5 smd: 1(-122,0) 2(122,0)
  silkscreen extent -175,-87 175,87
SMA_L4.3-W2.6-LS5.0-FD#1 [mil]
  rect 70.9x63.8 smd: 1(-84.7,-0.4) 2(84.6,0.4)
  silkscreen extent -86,-52 86,51
SMA_L4.3-W2.6-LS5.0-FD#2 [mil]
  rect 70.9x63.8 smd: 1(-84.7,-0.3) 2(84.6,0.4)
  silkscreen extent -85,-52 86,51
SMA_L4.3-W2.6-LS5.0-FD#3 [mil]
  rect 70.9x63.8 smd: 1(-84.7,-0.4) 2(84.6,0.3)
  silkscreen extent -86,-52 86,51
SMA_L4.3-W2.6-LS5.0-FD#4 [mil]
  rect 70.9x63.8 smd: 1(-84.6,-0.4) 2(84.6,0.4)
  silkscreen extent -85,-52 86,51
SMB_L4.6-W3.6-LS5.4-BI [mil]
  rect 80.6x88.2 smd: 1(-102,0) 2(102,0)
  silkscreen extent -105,-75 108,75
SOIC-8_L4.9-W3.9-P1.27-LS6.0-BL-EP2.3 [mil]
  oval 23.7x76.4 smd paste+0 mask+2: 1(-75,-107.1) 2(-25,-107.1) 3(25,-107.1) 4(75,-107.1) 5(75,107.1) 6(25,107.1) 7(-25,107.1) 8(-75,107.1)
  rect 90.2x90.2 smd paste+0 mask+2: 9(0,0)
  silkscreen extent -111,-113 99,60
SOIC-8_L5.0-W4.0-P1.27-LS6.0-BL [mil]
  oval 22.4x76.8 smd: 1(-75,-106.5) 2(-25,-106.5) 3(25,-106.5) 4(75,-106.5) 5(75,106.5) 6(25,106.5) 7(-25,106.5) 8(-75,106.5)
  silkscreen extent -98,-59 98,59
SOT-23-3_L2.9-W1.3-P1.90-LS2.4-BR [mil]
  rect 39.4x25.6 smd: 1(39.4,-37.4) 2(39.4,37.4) 3(-39.4,0)
  silkscreen extent -29,-60 29,60
SOT-23-3_L3.0-W1.7-P0.95-LS2.9-BR [mil]
  rect 40.8x20.9 smd: 1(43.4,-37.4) 2(43.4,37.4) 3(-43.4,0)
  silkscreen extent -34,-60 34,60
SOT-23-5_L3.0-W1.7-P0.95-LS2.8-BR [mil]
  rect 43.3x23.6 smd: 1(51.1,-37.4) 2(51.1,0) 3(51.1,37.4) 4(-51.2,37.4) 5(-51.2,-37.4)
  silkscreen extent -36,-61 35,61
SOT-23-6_L2.9-W1.6-P0.95-LS2.8-BR [mil]
  rect 43.3x23.6 smd paste+0 mask+2: 1(53.1,-37.4) 2(53.1,0) 3(53.1,37.4) 4(-53.2,37.4) 5(-53.2,0) 6(-53.2,-37.4)
  silkscreen extent -35,-70 60,61
TO-252-2_L6.6-W6.1-P4.57-LS9.9-TL-CW [mil]
  rect 110.2x51.2 smd: 1(-129.6,89.4) 3(-129.6,-89.5)
  rect 255.9x236.2 smd: 2(129.7,0)
  silkscreen extent -57,-132 178,131
TO-252-2_L6.6-W6.1-P4.57-LS10.1-TL-CW#1 [mil]
  rect 118.1x63 smd: 1(-134.8,90) 3(-134.8,-89.9)
  rect 244.1x228.3 smd: 2(134.8,0)
  silkscreen extent -54,-132 181,132
TO-252-2_L6.6-W6.1-P4.57-LS10.1-TL-CW#2 [mil]
  rect 118.1x63 smd: 1(-134.8,90) 3(-134.8,-90)
  rect 244.1x228.3 smd: 2(134.8,0)
  silkscreen extent -54,-132 180,132
VQFN-24_L4.0-W4.0-P0.50-TL-EP2.5 [mil]
  rect 23.6x9.8 smd paste-3937 mask+2: 1(-74.8,49.2) 2(-74.8,29.5) 3(-74.8,9.9) 4(-74.8,-9.8) 5(-74.8,-29.5) 6(-74.8,-49.2) 13(74.8,-49.2) 14(74.8,-29.5) 15(74.8,-9.8) 16(74.8,9.9) 17(74.8,29.5) 18(74.8,49.2)
  rect 9.8x23.6 smd paste-3937 mask+2: 7(-49.2,-74.8) 8(-29.5,-74.8) 9(-9.8,-74.8) 10(9.9,-74.8) 11(29.6,-74.8) 12(49.2,-74.8) 19(49.2,74.8) 20(29.6,74.8) 21(9.9,74.8) 22(-9.8,74.8) 23(-29.5,74.8) 24(-49.2,74.8)
  rect 96.5x96.5 smd paste-3937 mask+2: 25(0,0)
  silkscreen extent -105,-83 83,83

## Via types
v1: diameter 24, hole 12, Top Layer to Bottom Layer, 665 vias

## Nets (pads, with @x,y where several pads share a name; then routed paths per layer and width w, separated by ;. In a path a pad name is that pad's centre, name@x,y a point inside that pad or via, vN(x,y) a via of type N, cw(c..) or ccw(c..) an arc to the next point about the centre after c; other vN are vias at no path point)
3.3V: C17.2 C20.2 C22.2 C23.2 C24.2 C67.2 H4.1 R28.1 R30.2 R31.2 U3.1 U3.15 U3.31 U3.48 U3.64 U4.5 | length 976.9
  Top Layer w5.5: C17.2@4700.1,5367.6 v1(4701.1,5366.7) U4.5@4701.1,5305 4705,5305 4745,5265 4745,5223.3 R28.1@4747.4,5221 ; v1(5060,5219.3) 5159.3,5219.3 5175,5235 5240,5235 5290,5285 5432.8,5285 5432.8,5280 v1(5475.3,5237.6) 5478.1,5234.8 U3.31@5478.1,5188.1 ; v1(5077.1,5262.2) 5099.5,5284.6 U3.15@5125.7,5284.6 ; U3.1@5125.7,5560.1 5135.1,5560.1 v1(5161.9,5586.9) 5202.5,5627.5 U3.64@5202.5,5636.9 ; v1(5523.1,5557.9) 5571.4,5557.9 U3.48@5573.6,5560.1
  Bottom Layer w5.5: v1(5092.1,5588.2) 5095.3,5585 C24.2@5160,5585
  other v1: 4900.3,5805.7 4805,5810.3
3.3VA: C18.1 C19.1 C33.2 C41.2 C47.2 C53.2 D12.2 D13.2 D14.2 D15.2 R28.2 R36.2 R74.2 R80.2 R81.1 U3.28 U3.29 U6.8 U8.8 U9.8 U10.8 | length 582.2
  Top Layer w5.5: v1(5395,5135) 5419,5159 U3.28@5419,5188.1 U3.29@5438.7,5188.1 5438.7,5161.3 v1@5465,5135 ; U10.8@6106.5,4455 6160.9,4455 C53.2@6178.7,4472.8 v1(6217.2,4472.8) ; U8.8@6106.5,5125 6158.3,5125 v1(6181.2,5148) ; U6.8@6111.5,4785 6162,4785 C47.2@6188.7,4811.6 6223.4,4811.6 v1(6225,4810) ; U9.8@6116.5,3770 6177.8,3770 C33.2@6188.4,3780.5 6219.5,3780.5 v1@6220,3780
  other v1: 5649.7,3658.4 6220,3780.2 5593.4,4654.1 4670,5115.5 5013.8,5115.5 4499.6,5119.6 4839.6,5119.6 5465,5137.6 4747.4,5160 5780,5494.7
5V: C14.2 C16.2 C27.2 H2.1 H3.1 L1.2 OLED2.2 R21.2 U4.1 U4.3 U18.3 | length 3148.2
  Top Layer w5.5: C16.2@4535,5320 4534.6,5320.4 v1(4534.6,5322.6) ; U4.3@4598.8,5230.2 4514.8,5230.2 4500,5245 4500,5288 v1(4534.6,5322.6) ; U4.1@4598.8,5305 4552.2,5305 v1(4534.6,5322.6) ; v1(5494.2,5790.1) 5644.9,5790.1 5655,5780 v1(5655,5640) ; C27.2@5715,5645 5781.3,5645 U18.3@5783.3,5647
  Bottom Layer w5.5: v1(4528.1,5697.9) 4640,5697.9 ; v1@4535,5320 4825.3,5320 4860.3,5355 4860.3,5697.9 ; v1@4555.9,5670.5 4689.5,5670.5 v1(4835,5525) ; H2.1@4605,5945 4640,5910 4640,5697.9 ; H3.1@5015,5840 5015,5747 ; OLED2.2@5315,5730.1 5315,5789.9 5314.9,5790 ; v1(5494.2,5790.1) 5315,5790.1 5314.9,5790 ; v1(5655,5640) 5660,5645 v1@5715,5645 ; 4640,5697.9 4860.3,5697.9 ; 4860.3,5697.9 4872.9,5697.9 4922,5747 5015,5747 ; 5015,5747 5137,5747 5180,5790 5314.9,5790
  other v1: 5711.3,5642.4 4502.2,5672.2 4528.2,5672.1 4555.8,5671.8 4502.2,5697.6
12V: C10.2 C11.2 C12.2 C32.2 L3.2 R19.2 U2.3 U2.5 U7.4 | length 4068.3
  Top Layer w5.5: v1(3992.5,5222.5) 3993.6,5221.4 R19.2@3993.6,5168.4
  Bottom Layer w5.5: v1@3718.2,5637.9 3701.1,5655 3701.1,5894.2 3758.1,5951.3 4063.8,5951.3 4156.1,5858.9 4156.1,5436.1 4045,5325 4045,5275 v1(3992.5,5222.5) ; v1(4616.4,5459.1) 4682.7,5459.1 v1@4719.5,5495.9
  Bottom Layer w22: v1(4272.8,5204.9) 4273.2,5205.2 4330.2,5205.2 4614.8,4920.6 5530,4920.6 5630,4820.6 5630,4640 5590,4600 5590,4280 5800.2,4069.8 v1(5840,4069.8)
  other v1: 5818.8,4056.6 5818.9,4082.6 4216.9,5205.1 4245.5,5204.9 4216.9,5230.2 4245.5,5230 4273.1,5230 4245.5,5254.9 4272.8,5254.9 4498.7,5429.6 4524.7,5429.6 4549.8,5442.6 4498.7,5455 4524.5,5455.4 4721.9,5496.2 3667.2,5611.3 3691.9,5611 3719.6,5611 3745.4,5611 3773.1,5611 3692.1,5636.1 3719.6,5636.1 3745.7,5636.1 3773.1,5636.1
$1N4: CN1.2 DC1.4 F1.1
$1N41: D5.1 R2.1 R3.1 | length 184.6
  Top Layer w5.5: D5.1@3920,4482 D5.1@3923.3,4482 ; R2.1@3985.7,4419.7 D5.1@3923.3,4482 ; R3.1@3990.3,4545 3927.3,4482 D5.1@3923.3,4482
$1N50: C1.2 Q4.1 R3.2 R9.1 | length 250
  Top Layer w5.5: Q4.1@4050.6,4432.4 4043.6,4432.4 R3.2@3990.3,4485.7 3998.4,4485.7 C1.2@4062.6,4549.9 4130.2,4549.9 R9.1@4131,4550.7
$1N61: C1.1 D4.2 Q4.3 R4.1 R5.2 | length 431.9
  Top Layer w5.5: C1.1@4062.6,4494.8 4129.4,4427.9 Q4.3@4129.4,4395 ; D4.2@4200,4271.9 4129.4,4342.6 Q4.3@4129.4,4395 ; R5.2@4265.3,4429.3 4262.9,4431.7 R4.1@4195.9,4431.7 4166.1,4431.7 Q4.3@4129.4,4395
$1N70: C3.2 R7.1 | length 72.7
  Top Layer w5.5: C3.2@3907.6,4290 R7.1@3980.3,4290
$1N71: C4.2 R8.1 | length 63
  Top Layer w5.5: R8.1@4262.3,4551.9 4262.3,4614.7 C4.2@4262.4,4614.9
$1N73: LED1.2 R10.1 | length 58.2
  Top Layer w5.5: LED1.2@4195.8,4607.7 4195.9,4607.6 R10.1@4195.9,4549.5
$1N127: CN2.1 Q1.3
$1N135: C7.2 R13.1 R23.1 R24.2 U5.1 | length 367
  Top Layer w5.5: U5.1@4216.6,5042.4 4321.5,4937.6 C7.2@4335,4937.6 4335,4870.1 R24.2@4332.6,4867.8 4309.7,4844.9 R13.1@4264.1,4844.9 R23.1@4264.1,4788.5
$1N137: Q1.1 R26.2 | length 268.5
  Top Layer w5.5: Q1.1@3927.7,5044.3 3941.9,5030 4055,5030 4074.3,5010.7 R26.2@4074.3,4902.7
$1N158: C3.1 CN1.1 D2.1 DC1.2 DC1.3 Q6.2 | length 207.1
  Top Layer w5.5: Q6.2@3659.8,4255 3694.8,4290 C3.1@3852.4,4290
$1N168: D1.1 Q6.1 R1.1 | length 221.1
  Top Layer w5.5: Q6.1@3749.8,4524.6 3749.8,4513.3 D1.1@3840,4423.1 3843.8,4419.3 R1.1@3920.7,4419.3
$1N169: D2.2 D4.1 F1.2 Q2.3 Q4.2 R1.2 R2.2 R7.2 | length 351.1
  Top Layer w5.5: R1.2@3920.7,4360 3921,4360.3 R2.2@3985.7,4360.3 4047.9,4360.3 Q4.2@4050.6,4357.6 4039.7,4346.6 R7.2@4039.7,4290 4039.7,4237.4 D2.2@4107,4170
$1N172: LED2.2 R14.2 | length 56.4
  Top Layer w5.5: LED2.2@4134.8,4960.5 4135.3,4960 R14.2@4135.3,4904.3
$1N173: D6.2 Q5.3 R14.1 R26.1 | length 215.2
  Top Layer w5.5: D6.2@4010,4803.1 4034,4803.1 R26.1@4074.3,4843.4 ; Q5.3@4095,4779.4 4095,4822.6 R26.1@4074.3,4843.4 ; R14.1@4135.3,4845 4075.9,4845 R26.1@4074.3,4843.4
$1N174: R13.2 R16.2 U5.2 | length 151.5
  Top Layer w5.5: R16.2@4195.9,4904.7 4196.4,4904.2 R13.2@4264.1,4904.2 4264.1,4920.2 U5.2@4216.6,4967.6
$1N175: Q5.1 R15.1 R16.1 | length 230.4
  Top Layer w5.5: Q5.1@4057.6,4700.6 4097,4740 4145.6,4740 R15.1@4195.9,4790.4 R16.1@4195.9,4845.3
$1N177: Q2.1 R4.2 | length 149.4
  Top Layer w5.5: R4.2@4195.9,4372.4 4208.8,4372.4 Q2.1@4305.3,4275.8
$1N181: C8.1 U1.1
$1N182: R6.2 U1.4 | length 50.1
  Top Layer w5.5: R6.2@3667.2,5180.2 U1.4@3667.2,5230.3
$1N183: C9.2 U1.6 | length 77.3
  Top Layer w5.5: U1.6@3864.1,5286.3 3934.3,5286.3 C9.2@3939.3,5291.3
$1N188: C8.2 D16.2 L3.1 U1.8
  other v1: 3864.1,5386.3 3652.3,5484.4
$1N190: C11.1 R19.1 R20.2 U1.5 | length 183.2
  Top Layer w5.5: U1.5@3893.7,5235.1 3903.6,5225.3 C11.1@3938.6,5225.3 3938.6,5172.7 R19.1@3934.3,5168.4 ; C11.1@3939.7,5228.1 3992.9,5281.4 R20.2@3992.9,5281.7
$1N195: C15.1 U2.6
$1N197: C15.2 L1.1 U2.2
  other v1: 4551,5486.7 4577,5486.7 4603.3,5498.4 4550.9,5512.2 4576.8,5512.5 4325.5,5543.4 4351.5,5543.3 4379.1,5543 4325.4,5568.8 4351.3,5569.2 4637.9,5596
$1N199: R21.1 R22.2 U2.4 | length 115.1
  Top Layer w5.5: U2.4@4721.9,5458.8 4771,5458.8 R22.2@4773.7,5461.5 4832.3,5461.5 R21.1@4834.8,5464.1
$2N53: D3.1 Q3.1 R59.2 R84.2
$2N146: R55.2 R57.1 U9.2 | length 131.9
  Top Layer w5.5: R55.2@5831.4,3778.2 5831.4,3720.3 R57.1@5830.7,3719.6 5903.1,3719.6 U9.2@5903.5,3720
$2N147: R54.1 R56.1 U9.3 | length 233.4
  Top Layer w5.5: R56.1@5830.3,3660.7 5894.2,3660.7 U9.3@5903.5,3670 5930,3670 5975,3625 5975,3560.3 R54.1@5976.1,3559.2
$2N159: C36.2 R54.2 U9.6 U9.7 | length 285.1
  Top Layer w5.5: R54.2@6035.4,3559.2 6035.4,3615.4 6090,3670 U9.6@6116.5,3670 ; U9.7@6116.5,3720 U9.6@6116.5,3670 ; C36.2@6188.5,3662.4 6180.9,3670 U9.6@6116.5,3670
$2N177: R38.2 R55.1 U9.1 | length 161.6
  Top Layer w5.5: R55.1@5831.4,3837.5 5912.8,3837.5 R38.2@5915.3,3835 5915.3,3770.3 5915,3770 U9.1@5903.5,3770
$2N183: C42.2 R86.1 U8.6 U8.7 | length 290.7
  Top Layer w5.5: R86.1@6029,4910 6029,4980 6074,5025 U8.6@6106.5,5025 ; U8.7@6106.5,5075 U8.6@6106.5,5025 ; C42.2@6180.1,5027.4 6177.7,5025 U8.6@6106.5,5025
$2N190: R39.2 R87.1 U8.1 | length 145.3
  Top Layer w5.5: R87.1@5826.5,5203.9 R39.2@5892.5,5203.9 5893.5,5202.9 U8.1@5893.5,5125
$2N191: R87.2 R88.1 U8.2 | length 138.5
  Top Layer w5.5: R87.2@5826.5,5144.6 5826.5,5088.9 R88.1@5821.5,5083.9 5884.6,5083.9 U8.2@5893.5,5075
$2N192: R85.1 R86.2 U8.3 | length 230.9
  Top Layer w5.5: R85.1@5824.7,5025 U8.3@5893.5,5025 5920,5025 5965,4980 5965,4914.7 R86.2@5969.7,4910
$2N265: C68.2 R72.2 R80.1 R82.1 | length 2798.1
  Top Layer w5.5: v1(5538,5241) 5730.8,5241 v1(5789.9,5300.1) ; R72.2@5590.3,3600 R80.1@5590.3,3658.4 ; v1(5942,3897.5) 5943.3,3898.8 v1(6171.5,3898.8)
  Bottom Layer w5.5: R82.1@5348.3,5269.2 5408.5,5269.2 C68.2@5410.4,5271.1 5413.2,5268.2 5510.8,5268.2 v1(5538,5241) ; v1@5590.3,3658.4 5627,3695 5739.5,3695 v1(5942,3897.5) ; v1(5789.9,5300.1) 6175.8,4914.2 6175.8,3913.7 ; 6175.8,3913.7 6171.5,3909.4 v1(6171.5,3898.8) 6175.8,3903 6175.8,3913.7
  other v1: 5588.7,3658.4
$2N267: C69.2 R73.2 R74.1 R83.1 | length 866.3
  Top Layer w5.5: v1(5270,5015) 5475,5015 5655,4835 5655,4620 5628.1,4593.1 R74.1@5593.4,4593.1 R73.2@5593.4,4535.8
  Bottom Layer w5.5: R83.1@5267.7,5077.2 5267.7,5016.5 C69.2@5268.4,5015.8
$2N268: D7.1 Q7.1 R60.2 R61.2
$2N270: D8.1 Q8.1 R62.2 R63.2
$2N271: D9.1 Q9.1 R64.2 R75.2
$2N276: D10.1 Q10.1 R76.2 R77.2
$2N278: D11.1 Q11.1 R78.2 R79.2
$2N298: C48.2 R43.1 U6.6 U6.7 | length 303.1
  Top Layer w5.5: R43.1@6026.5,4575 6026.5,4650 6061.5,4685 U6.6@6111.5,4685 ; U6.7@6111.5,4735 U6.6@6111.5,4685 ; C48.2@6188.7,4688.4 6185.3,4685 U6.6@6111.5,4685
$2N305: R40.2 R45.1 U6.1 | length 154.4
  Top Layer w5.5: R45.1@5826.5,4850 R40.2@5910.8,4850 5910.8,4797.3 U6.1@5898.5,4785
$2N306: R45.2 R46.1 U6.2 | length 137.3
  Top Layer w5.5: R45.2@5826.5,4790.7 5824.7,4788.9 R46.1@5824.7,4730 5893.5,4730 U6.2@5898.5,4735
$2N307: R42.1 R43.2 U6.3 | length 241.9
  Top Layer w5.5: R42.1@5824.7,4665 5844.7,4685 U6.3@5898.5,4685 5935,4685 5965,4655 5965,4577.1 R43.2@5967.1,4575
$2N312: C54.2 R50.1 U10.6 U10.7 | length 281.3
  Top Layer w5.5: R50.1@6030.1,4246.1 6030.1,4310 6075.1,4355 U10.6@6106.5,4355 ; U10.7@6106.5,4405 U10.6@6106.5,4355 ; C54.2@6178.7,4354.5 6178.1,4355 U10.6@6106.5,4355
$2N319: R47.2 R52.1 U10.1 | length 155.3
  Top Layer w5.5: R52.1@5821.5,4526.1 R47.2@5902.1,4526.1 5902.1,4463.6 U10.1@5893.5,4455
$2N320: R52.2 R53.1 U10.2 | length 131
  Top Layer w5.5: R52.2@5821.5,4466.8 5825.1,4463.1 R53.1@5825.1,4406.1 5892.4,4406.1 U10.2@5893.5,4405
$2N321: R48.1 R50.2 U10.3 | length 232.3
  Top Layer w5.5: R48.1@5824.7,4345 5883.5,4345 U10.3@5893.5,4355 5925,4355 5970,4310 5970,4246.9 R50.2@5970.8,4246.1
$3N117: CN12.1 R25.2 U18.7 | length 398.6
  Top Layer w5.5: CN12.1@5925,5950 5925,5725 5953,5697 U18.7@5996.3,5697 6045.1,5697 R25.2@6074.8,5667.4
$3N118: CN12.2 R29.1 U18.6 | length 505.8
  Top Layer w5.5: CN12.2@5775,5950 5775,5845 5973,5647 U18.6@5996.3,5647 6030.1,5647 R29.1@6075.1,5602
$3N119: C28.2 R25.1 R29.2 | length 136.1
  Top Layer w5.5: C28.2@6131.3,5736.8 6134.1,5734 R25.1@6134.1,5667.4 6134.4,5667 R29.2@6134.4,5602
ADC_AI: C46.2 R39.1 U3.8 | length 1116.4
  Top Layer w5.5: U3.8@5125.7,5422.3 5167.3,5422.3 5175,5430 5175,5470 5210,5505 5315,5505 5515,5305 5515,5234.7 5550.2,5199.5 5747.8,5199.5 5828.3,5280 5875.7,5280 R39.1@5951.8,5203.9
  other v1: 5172.6,5470
ADC_AU: C21.2 D12.1 R58.1 R65.2 U3.12 | length 887.4
  Top Layer w5.5: D12.1@5010.4,4950.4 5076,4950.4 R58.1@5093.3,4933 v1(5093.3,4992.7) ; U3.12@5125.7,5343.6 v1(5180,5343.6)
  Bottom Layer w5.5: v1@5093.3,4995 5103.5,5005.2 5103.5,5151.9 5173.5,5221.8 5296.8,5221.8 5320,5245 5320,5355 5305,5370 5206.4,5370 v1(5180,5343.6)
ADC_BI: C52.2 R40.1 U3.9 | length 1212.4
  Top Layer w5.5: U3.9@5125.7,5402.7 5126.8,5403.7 v1(5178,5403.7) ; R40.1@5970.1,4850 v1(6020,4850)
  Bottom Layer w5.5: v1(5178,5403.7) 5178,5413 5208.5,5443.5 5426.5,5443.5 v1(6020,4850)
ADC_BU: C61.2 D13.1 R66.1 R67.2 U3.13 | length 875.3
  Top Layer w5.5: D13.1@4840.4,4950.4 4906.9,4950.4 R66.1@4924.3,4933 4926.3,4935 v1(4926.3,4993) ; U3.13@5125.7,5323.9 5169.4,5323.9 5191.5,5301.8 5191.5,5300 5195.4,5296.1 5251.1,5296.1 v1@5290,5335
  Bottom Layer w5.5: v1@4924.2,4995.8 5166.7,5238.3 5189.4,5238.3 5199.8,5248.8 5199.8,5289.8 5210,5300 5255,5300 C61.2@5290,5335
  other v1: 5291.2,5335.1
ADC_CI: C58.2 R47.1 U3.10 | length 1575
  Top Layer w5.5: U3.10@5125.7,5383 5273,5383 v1(5290,5400) ; R47.1@5961.5,4526.1 5966.5,4521.1 v1(6058.8,4521.1)
  Bottom Layer w5.5: C58.2@5292.1,5400.1 5319,5427 5410.9,5427 6058.8,4779.2 v1(6058.8,4521.1)
ADC_CU: C63.2 D14.1 R68.1 R69.2 U3.14 | length 766
  Top Layer w5.5: D14.1@4670.4,4950.4 4740.1,4950.4 R68.1@4757.4,4933 4757.4,4992 R69.2@4756.7,4992.7 ; U3.14@5125.7,5304.2 5165.8,5304.2 5175,5295 v1(5175,5274)
  Bottom Layer w5.5: v1(4755,4990) 4930,5165 5066,5165 v1(5175,5274)
ADC_I: C40.2 R38.1 U3.18 | length 2369.2
  Top Layer w5.5: v1(5140,5140) 5149.8,5149.8 5208.5,5149.8 5222.2,5163.4 U3.18@5222.2,5188.1 ; R38.1@5974.7,3835 v1(6043.3,3835)
  Bottom Layer w5.5: v1(5140,5140) 5175,5105 5175,4985 5186.6,4973.4 5498.4,4973.4 5645,5120 5694.6,5120 6038,4776.6 6038,3840.3 v1(6043.3,3835)
ADC_NTC1: R82.2 U3.20 | length 85.8
  Top Layer w5.5: U3.20@5261.5,5188.1 5261.5,5226.5 v1(5295,5260)
ADC_NTC2: R83.2 U3.21 | length 57.7
  Top Layer w5.5: v1@5270,5135 5281.2,5146.2 U3.21@5281.2,5188.1
  other v1: 5267.7,5136.5
ADC_Speed: C70.2 R81.2 U3.22 | length 100.9
  Top Layer w5.5: U3.22@5300.9,5188.1 5300.9,5163.4 5314.5,5149.8 5315.2,5149.8 5330,5135
  Bottom Layer w5.5: C70.2@5330,5135 5355,5110
ADC_SPEED:  | length 878.3
  Top Layer w5.5: v1(5575,5220.2) 5745.2,5220.2 5825,5300 6025,5300 6100,5375
  Bottom Layer w5.5: 5355,5110 5505,5110 5575,5180 v1(5575,5220.2)
  other v1: 5330,5135
ADC_U: C64.2 D15.1 R70.1 R71.2 U3.19 | length 950.3
  Top Layer w5.5: D15.1@4508.6,4945.6 4572.7,4945.6 R70.1@4586.1,4932.1 ; R70.1@4584.8,4934.1 4584.8,4984 R71.2@4587.9,4987.2 ; R71.2@4590,4990 4625,4990 4812.6,5177.6 5042.4,5177.6 5105,5115 5191.9,5115 v1(5205,5128.1) 5228.1,5128.1 5241.8,5141.8 U3.19@5241.8,5188.1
